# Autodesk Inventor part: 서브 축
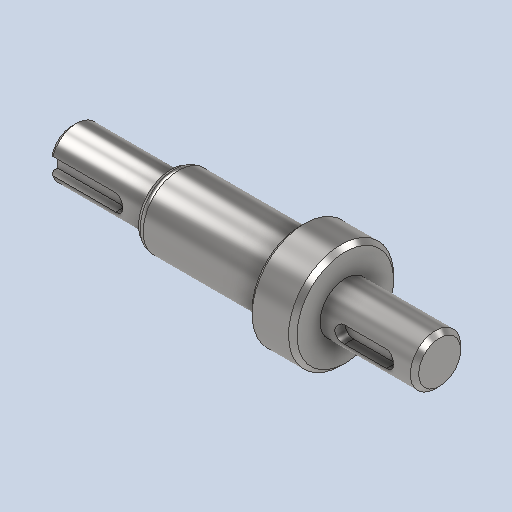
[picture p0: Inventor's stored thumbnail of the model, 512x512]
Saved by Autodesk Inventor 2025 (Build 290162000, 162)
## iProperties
Created: 2024-07
Part Number: 서브 축
Material: 강철, 연강
Document SubType Name: Modeling
Designer: hsj03
Density: 7.86 g/cm^3
Appearance: 기본값
Author: jhkim
Revision Number: 1
Sending System: Autodesk Inventor 2025
Preprocessor: ST-DEVELOPER v20
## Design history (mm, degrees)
feature "솔리드1"
node "솔리드2"
